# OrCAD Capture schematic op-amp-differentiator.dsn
size A
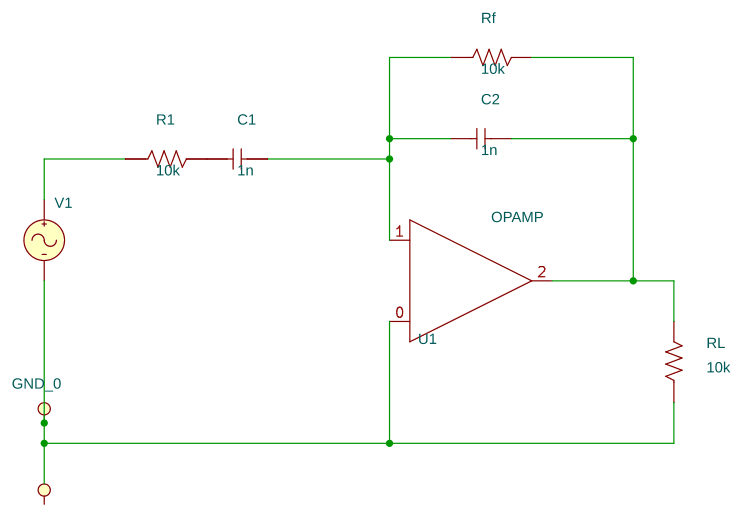
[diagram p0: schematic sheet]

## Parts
C1  1n  [cap196]
C2  1n  [cap196]
R1  10k  [AXRC05]
Rf  10k  [AXRC05]
RL  10k  [AXRC05]
U1  OPAMP
V1  VAC

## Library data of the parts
C1 C2 = C
R1 Rf RL = R
U1 = OPAMP
V1 = VAC

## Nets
0: RL.1 U1.0(+) V1.2(-)
N15135: C1.2 C2.1 Rf.1 U1.1(-)
N15143: C2.2 Rf.2 RL.2 U1.2(OUT)
N15199: R1.1 V1.1(+)
N15520: C1.1 R1.2
